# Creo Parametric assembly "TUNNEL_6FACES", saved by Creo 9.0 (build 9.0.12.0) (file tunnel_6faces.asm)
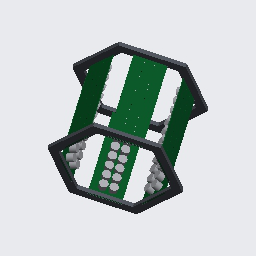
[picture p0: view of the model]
Units: millimeter Newton Second (mmNs); MM, TONNE, SECS

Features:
  1. coordinate system "TUNNEL_6FACES"
  2. imported feature "Import Feature id 4"
  3. component "TUNNEL_6FACES_1"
